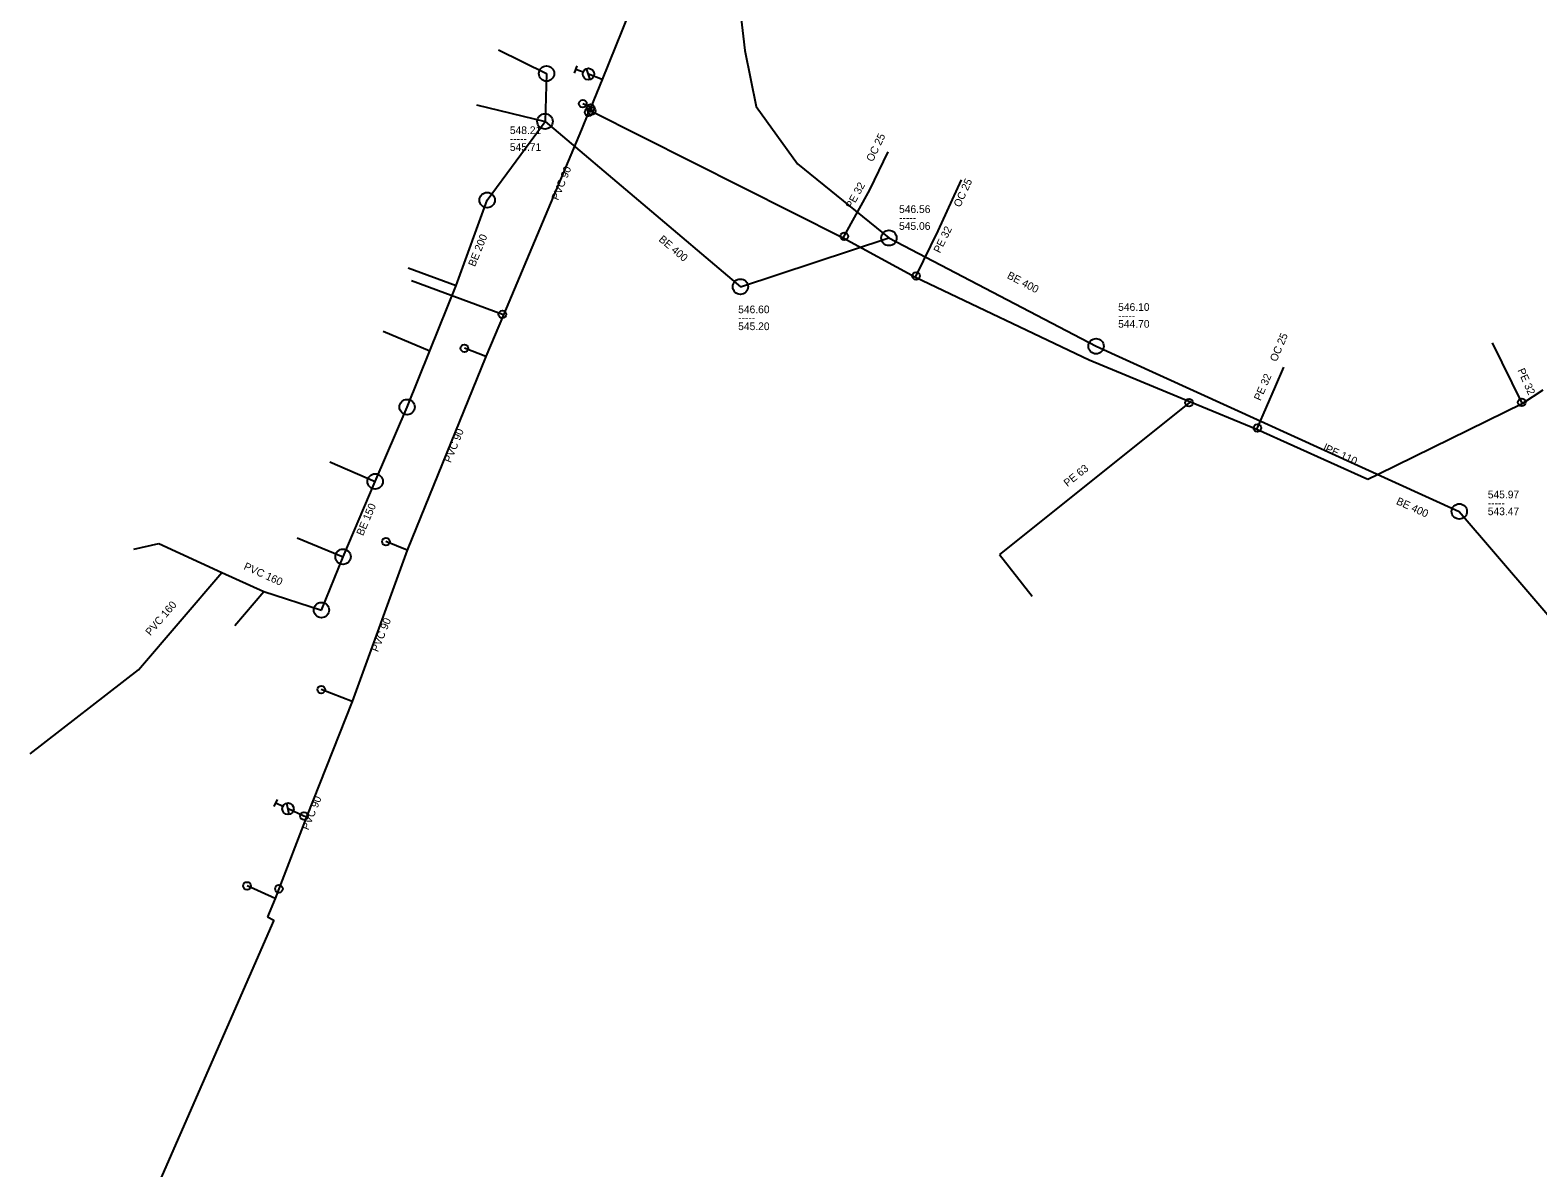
# Model space of a CAD drawing. Extents: x -701133 to -700495, y -1142806 to -1142020.
# Drawn here: x -700897.3 to -700700.7, y -1142526.7 to -1142378.4 of the extents above; entities that cross this region are included whole.
import ezdxf

# ---------------------------------------------------------------- set-up
doc = ezdxf.new("R2010")
doc.units = 0
doc.layers.add('Level 0', color=7, linetype='Continuous')

msp = doc.modelspace()

# ---------------------------------------------------------------- linework, layer by layer
at = {"layer": 'Level 0'}
for p, q in [((-700815.87, -1142367.89), (-700822.71, -1142384.8)), ((-700805.42, -1142369.82), (-700804.11, -1142381.01)), ((-700836.23, -1142380.93), (-700829.95, -1142384.01)), ((-700804.11, -1142381.01), (-700802.61, -1142388.33)), ((-700826.31, -1142383.95), (-700825.96, -1142383.01)), ((-700824.26, -1142384.79), (-700824.72, -1142383.37)), ((-700829.95, -1142384.01), (-700830.15, -1142390.25)), ((-700825.19, -1142383.82), (-700826.13, -1142383.48)), ((-700822.71, -1142384.8), (-700824.49, -1142384.08)), ((-700822.71, -1142384.8), (-700824.16, -1142388.38)), ((-700839.1, -1142388.11), (-700830.15, -1142390.25)), ((-700824.46, -1142389.05), (-700825.39, -1142391.29)), ((-700824.16, -1142388.38), (-700825.22, -1142387.95)), ((-700824.34, -1142388.77), (-700824.46, -1142389.05)), ((-700824.21, -1142388.5), (-700824.34, -1142388.77)), ((-700824.34, -1142388.77), (-700824.07, -1142388.9)), ((-700824.16, -1142388.38), (-700824.21, -1142388.5)), ((-700824.07, -1142388.9), (-700791.28, -1142405.45)), ((-700802.61, -1142388.33), (-700797.25, -1142395.77)), ((-700837.69, -1142400.51), (-700830.15, -1142390.25)), ((-700825.39, -1142391.29), (-700835.56, -1142415.46)), ((-700830.15, -1142390.25), (-700804.68, -1142411.8)), ((-700787.83, -1142399.16), (-700785.44, -1142394.22)), ((-700797.25, -1142395.77), (-700785.32, -1142405.45)), ((-700791.15, -1142405.22), (-700787.83, -1142399.16)), ((-700778.9, -1142404.52), (-700775.88, -1142397.87)), ((-700841.72, -1142411.65), (-700837.69, -1142400.51)), ((-700781.78, -1142410.39), (-700778.9, -1142404.52)), ((-700804.68, -1142411.8), (-700785.32, -1142405.45)), ((-700791.28, -1142405.45), (-700791.15, -1142405.22)), ((-700791.28, -1142405.45), (-700781.87, -1142410.57)), ((-700785.32, -1142405.45), (-700758.32, -1142419.56)), ((-700847.99, -1142409.36), (-700841.72, -1142411.65)), ((-700781.87, -1142410.57), (-700781.78, -1142410.39)), ((-700781.87, -1142410.57), (-700759.23, -1142421.34)), ((-700835.7, -1142415.41), (-700847.57, -1142411.05)), ((-700845.16, -1142420.17), (-700841.72, -1142411.65)), ((-700835.56, -1142415.46), (-700837.85, -1142420.91)), ((-700835.56, -1142415.46), (-700835.7, -1142415.41)), ((-700851.24, -1142417.59), (-700845.16, -1142420.17)), ((-700848.12, -1142427.49), (-700845.16, -1142420.17)), ((-700837.85, -1142420.91), (-700840.65, -1142419.82)), ((-700758.32, -1142419.56), (-700710.97, -1142441.1)), ((-700702.83, -1142426.88), (-700706.65, -1142419.12)), ((-700837.85, -1142420.91), (-700848.12, -1142446.14)), ((-700759.23, -1142421.34), (-700746.02, -1142426.79)), ((-700734.93, -1142424.83), (-700733.85, -1142422.27)), ((-700737.29, -1142430.22), (-700734.93, -1142424.83)), ((-700702.68, -1142426.98), (-700700.02, -1142425.26)), ((-700852.29, -1142437.19), (-700848.12, -1142427.49)), ((-700746.19, -1142426.92), (-700770.91, -1142446.73)), ((-700746.02, -1142426.79), (-700746.19, -1142426.92)), ((-700746.02, -1142426.79), (-700737.36, -1142430.37)), ((-700721.54, -1142436.23), (-700702.68, -1142426.98)), ((-700702.68, -1142426.98), (-700702.83, -1142426.88)), ((-700737.36, -1142430.37), (-700737.29, -1142430.22)), ((-700737.36, -1142430.37), (-700722.91, -1142436.91)), ((-700858.21, -1142434.64), (-700852.29, -1142437.19)), ((-700722.91, -1142436.91), (-700721.54, -1142436.23)), ((-700856.48, -1142447), (-700852.29, -1142437.19)), ((-700710.97, -1142441.1), (-700671.71, -1142486.99)), ((-700883.74, -1142446.04), (-700880.48, -1142445.3)), ((-700880.48, -1142445.3), (-700872.28, -1142449.06)), ((-700862.47, -1142444.56), (-700856.48, -1142447)), ((-700848.12, -1142446.14), (-700855.28, -1142465.87)), ((-700848.12, -1142446.14), (-700850.89, -1142445.04)), ((-700859.29, -1142453.95), (-700856.48, -1142447)), ((-700770.91, -1142446.73), (-700766.63, -1142452.15)), ((-700883.15, -1142461.74), (-700872.28, -1142449.06)), ((-700872.28, -1142449.06), (-700866.78, -1142451.54)), ((-700870.6, -1142455.98), (-700866.78, -1142451.54)), ((-700866.78, -1142451.54), (-700859.29, -1142453.95)), ((-700897.26, -1142472.7), (-700883.15, -1142461.74)), ((-700855.28, -1142465.87), (-700861.25, -1142480.91)), ((-700855.28, -1142465.87), (-700859.32, -1142464.32)), ((-700865.45, -1142479.58), (-700865.03, -1142478.67)), ((-700864.33, -1142479.55), (-700865.24, -1142479.13)), ((-700863.48, -1142480.59), (-700863.82, -1142479.13)), ((-700861.25, -1142480.91), (-700864.84, -1142490.3)), ((-700861.57, -1142480.82), (-700863.65, -1142479.86)), ((-700861.25, -1142480.91), (-700861.57, -1142480.82)), ((-700865.32, -1142491.54), (-700868.99, -1142489.91)), ((-700865.32, -1142491.54), (-700866.31, -1142493.95)), ((-700864.84, -1142490.3), (-700865.32, -1142491.54)), ((-700865.49, -1142494.38), (-700880.96, -1142529.72)), ((-700866.31, -1142493.95), (-700865.49, -1142494.38))]:
    msp.add_line(p, q, dxfattribs=at)
for centre, radius in [((-700829.95, -1142384.01), 1), ((-700824.49, -1142384.08), 0.75), ((-700830.15, -1142390.25), 1), ((-700825.22, -1142387.95), 0.5), ((-700824.46, -1142389.05), 0.5), ((-700824.21, -1142388.5), 0.5), ((-700824.07, -1142388.9), 0.5), ((-700837.69, -1142400.51), 1), ((-700791.15, -1142405.22), 0.5), ((-700785.32, -1142405.45), 1), ((-700804.68, -1142411.8), 1), ((-700781.78, -1142410.39), 0.5), ((-700835.7, -1142415.41), 0.5), ((-700758.32, -1142419.56), 1), ((-700840.65, -1142419.82), 0.5), ((-700848.12, -1142427.49), 1), ((-700746.19, -1142426.92), 0.5), ((-700702.83, -1142426.88), 0.5), ((-700737.29, -1142430.22), 0.5), ((-700852.29, -1142437.19), 1), ((-700710.97, -1142441.1), 1), ((-700856.48, -1142447), 1), ((-700850.89, -1142445.04), 0.5), ((-700859.29, -1142453.95), 1), ((-700859.32, -1142464.32), 0.5), ((-700863.65, -1142479.86), 0.75), ((-700861.57, -1142480.82), 0.5), ((-700868.99, -1142489.91), 0.5), ((-700864.84, -1142490.3), 0.5)]:
    msp.add_circle(centre, radius, dxfattribs=at)

# ---------------------------------------------------------------- texts
for s, p in [('548.21', (-700834.73, -1142391.9)), ('545.71', (-700834.73, -1142394.1)), ('-----', (-700834.73, -1142393)), ('546.56', (-700784, -1142402.19)), ('-----', (-700784, -1142403.29)), ('545.06', (-700784, -1142404.39)), ('546.60', (-700804.97, -1142415.26)), ('546.10', (-700755.44, -1142414.95)), ('545.20', (-700804.97, -1142417.46)), ('-----', (-700804.97, -1142416.36)), ('544.70', (-700755.44, -1142417.15)), ('-----', (-700755.44, -1142416.05)), ('545.97', (-700707.26, -1142439.39)), ('-----', (-700707.26, -1142440.49)), ('543.47', (-700707.26, -1142441.59))]:
    msp.add_text(s, height=1, dxfattribs=at).set_placement(p)
for s, rotation, p in [('OC 25', 64.182, (-700787.43, -1142395.6)), ('PVC 90', 67.851, (-700828.43, -1142400.62)), ('PE 32', 61.284, (-700790.14, -1142401.73)), ('OC 25', 65.576, (-700776.03, -1142401.52)), ('BE 200', 68.013, (-700839.28, -1142409.27)), ('BE 400', 319.766, (-700815.41, -1142405.77)), ('PE 32', 63.866, (-700778.67, -1142407.5)), ('BE 400', 332.409, (-700770.01, -1142410.65)), ('OC 25', 67.126, (-700734.79, -1142421.66)), ('PE 32', 293.711, (-700703.41, -1142422.69)), ('PE 32', 66.354, (-700736.88, -1142426.75)), ('PVC 90', 67.851, (-700842.44, -1142434.83)), ('lPE 110', 335.649, (-700728.81, -1142433.14)), ('lPE 110', 335.649, (-700728.81, -1142433.14)), ('lPE 110', 335.649, (-700728.81, -1142433.14)), ('PE 63', 38.708, (-700762.05, -1142437.94)), ('BE 150', 66.872, (-700853.87, -1142444.35)), ('BE 400', 335.539, (-700719.28, -1142440.11)), ('PVC 160', 335.729, (-700869.51, -1142448.61)), ('PVC 160', 49.395, (-700881.58, -1142457.38)), ('PVC 90', 67.851, (-700851.92, -1142459.5)), ('PVC 90', 67.668, (-700861, -1142482.72))]:
    msp.add_text(s, height=1, rotation=rotation, dxfattribs=at).set_placement(p)

doc.saveas('drawing.dxf')
